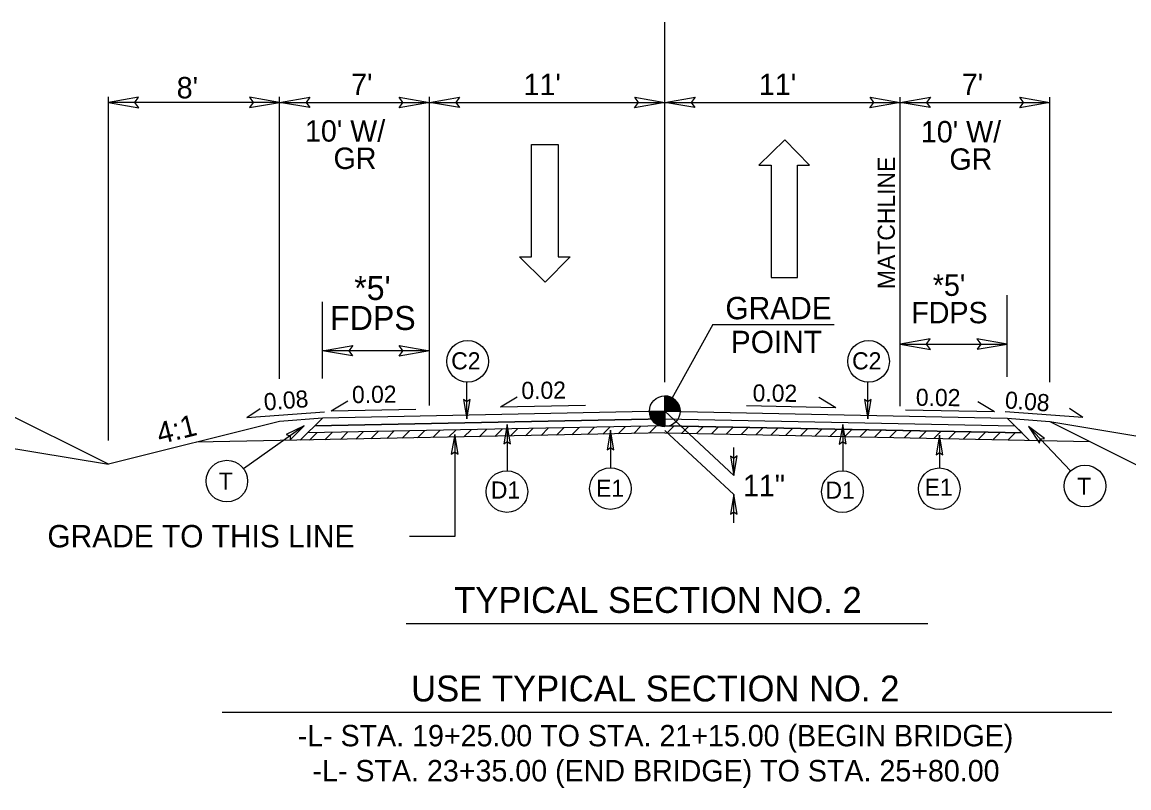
# Model space of a CAD drawing. Extents: x 1184121 to 1184397, y 1246506 to 1246661.
# Drawn here: x 1184197.8 to 1184249.5, y 1246556.8 to 1246592.6 of the extents above; entities that cross this region are included whole.
import ezdxf

# ---------------------------------------------------------------- set-up
doc = ezdxf.new("R2010")
doc.units = 0
doc.layers.add('Prop Shade Light', color=7, linetype='Continuous')
doc.layers.add('Sheet Data Field CELL', color=7, linetype='Continuous')

msp = doc.modelspace()

# ---------------------------------------------------------------- linework, layer by layer
at = {"layer": 'Prop Shade Light'}
msp.add_lwpolyline([(1184244.482, 1246573.385), (1184227.785, 1246573.719), (1184211.092, 1246573.385), (1184211.428, 1246573.722), (1184227.787, 1246574.049), (1184244.145, 1246573.722)], close=True, dxfattribs=at)
at = {"layer": 'Sheet Data Field CELL'}
for p, q in [((1184227.787, 1246575.765), (1184227.787, 1246592.571)), ((1184201.787, 1246573.031), (1184201.787, 1246589.086)), ((1184209.787, 1246575.906), (1184209.787, 1246589.086)), ((1184216.787, 1246574.661), (1184216.787, 1246589.086)), ((1184238.787, 1246574.633), (1184238.787, 1246589.069)), ((1184245.787, 1246575.765), (1184245.787, 1246589.069)), ((1184209.787, 1246588.821), (1184201.787, 1246588.821)), ((1184209.787, 1246588.821), (1184216.787, 1246588.821)), ((1184216.787, 1246588.821), (1184227.787, 1246588.821)), ((1184227.787, 1246588.821), (1184238.787, 1246588.821)), ((1184238.787, 1246588.821), (1184245.787, 1246588.821)), ((1184221.564, 1246581.612), (1184221.564, 1246586.862)), ((1184221.564, 1246586.862), (1184222.802, 1246586.862)), ((1184222.802, 1246586.862), (1184222.802, 1246581.612)), ((1184233.389, 1246587.079), (1184232.189, 1246585.898)), ((1184234.552, 1246585.898), (1184233.389, 1246587.079)), ((1184232.189, 1246585.898), (1184232.752, 1246585.898)), ((1184232.752, 1246585.898), (1184232.752, 1246580.648)), ((1184233.989, 1246580.648), (1184233.989, 1246585.898)), ((1184233.989, 1246585.898), (1184234.552, 1246585.898)), ((1184222.202, 1246580.431), (1184221.002, 1246581.612)), ((1184221.002, 1246581.612), (1184221.564, 1246581.612)), ((1184223.364, 1246581.612), (1184222.202, 1246580.431)), ((1184222.802, 1246581.612), (1184223.364, 1246581.612)), ((1184232.752, 1246580.648), (1184233.989, 1246580.648)), ((1184243.787, 1246576.013), (1184243.787, 1246579.818)), ((1184211.787, 1246575.934), (1184211.787, 1246579.506)), ((1184230.037, 1246578.445), (1184227.787, 1246574.4)), ((1184230.037, 1246578.445), (1184235.698, 1246578.445)), ((1184201.787, 1246571.92), (1184189.629, 1246577.999)), ((1184216.787, 1246577.224), (1184211.787, 1246577.224)), ((1184238.787, 1246577.537), (1184243.787, 1246577.537)), ((1184218.537, 1246574.038), (1184218.537, 1246575.759)), ((1184237.274, 1246574.038), (1184237.274, 1246575.759)), ((1184220.109, 1246574.605), (1184220.892, 1246575.078)), ((1184227.787, 1246574.4), (1184227.787, 1246575.116)), ((1184235.772, 1246574.565), (1184234.989, 1246575.039)), ((1184208.255, 1246574.104), (1184208.875, 1246574.532)), ((1184212.193, 1246574.414), (1184212.976, 1246574.887)), ((1184212.193, 1246574.414), (1184216.158, 1246574.493)), ((1184220.109, 1246574.605), (1184224.074, 1246574.684)), ((1184235.772, 1246574.565), (1184231.607, 1246574.649)), ((1184243.193, 1246574.367), (1184239.029, 1246574.45)), ((1184243.193, 1246574.367), (1184242.41, 1246574.84)), ((1184247.319, 1246574.104), (1184246.698, 1246574.532)), ((1184189.629, 1246573.946), (1184201.787, 1246571.92)), ((1184208.255, 1246574.104), (1184211.88, 1246574.376)), ((1184211.787, 1246574.08), (1184209.787, 1246573.92)), ((1184211.787, 1246574.08), (1184210.751, 1246573.045)), ((1184227.787, 1246574.049), (1184211.428, 1246573.722)), ((1184227.787, 1246574.4), (1184211.787, 1246574.08)), ((1184227.071, 1246574.4), (1184227.787, 1246574.4)), ((1184227.785, 1246573.684), (1184227.787, 1246574.4)), ((1184227.787, 1246574.4), (1184227.785, 1246573.684)), ((1184228.503, 1246574.4), (1184227.787, 1246574.4)), ((1184227.787, 1246574.4), (1184243.787, 1246574.08)), ((1184227.787, 1246574.4), (1184231.014, 1246571.4)), ((1184227.787, 1246574.049), (1184244.145, 1246573.722)), ((1184247.319, 1246574.104), (1184243.694, 1246574.376)), ((1184243.787, 1246574.08), (1184245.787, 1246573.92)), ((1184243.787, 1246574.08), (1184244.822, 1246573.044)), ((1184209.787, 1246573.92), (1184201.787, 1246571.92)), ((1184210.93, 1246573.715), (1184208.1, 1246571.717)), ((1184227.793, 1246573.719), (1184211.092, 1246573.385)), ((1184211.904, 1246573.068), (1184212.244, 1246573.408)), ((1184212.625, 1246573.082), (1184212.965, 1246573.422)), ((1184213.347, 1246573.097), (1184213.687, 1246573.437)), ((1184214.053, 1246573.111), (1184214.393, 1246573.451)), ((1184214.79, 1246573.125), (1184215.13, 1246573.466)), ((1184215.511, 1246573.14), (1184215.851, 1246573.48)), ((1184216.232, 1246573.154), (1184216.572, 1246573.494)), ((1184216.953, 1246573.169), (1184217.294, 1246573.509)), ((1184217.675, 1246573.183), (1184218.015, 1246573.523)), ((1184218.397, 1246573.198), (1184218.737, 1246573.538)), ((1184219.118, 1246573.212), (1184219.458, 1246573.552)), ((1184219.84, 1246573.226), (1184220.18, 1246573.567)), ((1184220.422, 1246573.785), (1184220.422, 1246571.619)), ((1184220.561, 1246573.241), (1184220.901, 1246573.581)), ((1184221.283, 1246573.255), (1184221.623, 1246573.595)), ((1184222.004, 1246573.27), (1184222.344, 1246573.61)), ((1184222.726, 1246573.284), (1184223.066, 1246573.624)), ((1184223.447, 1246573.299), (1184223.787, 1246573.639)), ((1184224.169, 1246573.313), (1184224.509, 1246573.653)), ((1184224.89, 1246573.327), (1184225.231, 1246573.668)), ((1184225.25, 1246573.508), (1184225.25, 1246571.762)), ((1184225.612, 1246573.342), (1184225.952, 1246573.682)), ((1184226.333, 1246573.356), (1184226.674, 1246573.696)), ((1184227.055, 1246573.371), (1184227.395, 1246573.711)), ((1184227.78, 1246573.719), (1184244.482, 1246573.385)), ((1184227.787, 1246573.507), (1184231.014, 1246570.507)), ((1184227.884, 1246573.383), (1184228.21, 1246573.71)), ((1184228.577, 1246573.369), (1184228.903, 1246573.696)), ((1184229.27, 1246573.356), (1184229.597, 1246573.682)), ((1184229.963, 1246573.342), (1184230.29, 1246573.668)), ((1184230.657, 1246573.328), (1184230.983, 1246573.654)), ((1184231.35, 1246573.314), (1184231.676, 1246573.641)), ((1184232.043, 1246573.3), (1184232.37, 1246573.627)), ((1184232.736, 1246573.286), (1184233.063, 1246573.613)), ((1184233.429, 1246573.272), (1184233.756, 1246573.599)), ((1184234.123, 1246573.258), (1184234.449, 1246573.585)), ((1184234.816, 1246573.245), (1184235.143, 1246573.571)), ((1184235.509, 1246573.231), (1184235.836, 1246573.557)), ((1184236.104, 1246573.779), (1184236.104, 1246571.613)), ((1184236.202, 1246573.217), (1184236.529, 1246573.543)), ((1184236.896, 1246573.203), (1184237.222, 1246573.53)), ((1184237.589, 1246573.189), (1184237.916, 1246573.516)), ((1184238.282, 1246573.175), (1184238.609, 1246573.502)), ((1184238.975, 1246573.161), (1184239.302, 1246573.488)), ((1184239.669, 1246573.148), (1184239.995, 1246573.474)), ((1184240.362, 1246573.134), (1184240.688, 1246573.46)), ((1184241.055, 1246573.12), (1184241.382, 1246573.446)), ((1184241.748, 1246573.106), (1184242.075, 1246573.433)), ((1184242.442, 1246573.092), (1184242.768, 1246573.419)), ((1184243.135, 1246573.078), (1184243.462, 1246573.405)), ((1184244.784, 1246573.685), (1184246.753, 1246571.611)), ((1184245.787, 1246573.92), (1184261.306, 1246571.333)), ((1184245.787, 1246573.92), (1184261.306, 1246566.16)), ((1184227.785, 1246573.385), (1184205.897, 1246572.948)), ((1184211.182, 1246573.053), (1184211.523, 1246573.393)), ((1184217.968, 1246573.307), (1184217.968, 1246568.548)), ((1184227.785, 1246573.385), (1184247.651, 1246572.988)), ((1184240.628, 1246573.275), (1184240.628, 1246571.75)), ((1184243.828, 1246573.064), (1184244.155, 1246573.391)), ((1184231.014, 1246571.4), (1184231.014, 1246572.706)), ((1184231.014, 1246569.191), (1184231.014, 1246570.507)), ((1184217.968, 1246568.548), (1184215.851, 1246568.548)), ((1184215.704, 1246564.485), (1184240.08, 1246564.485)), ((1184207.1, 1246560.35), (1184248.685, 1246560.35))]:
    msp.add_line(p, q, dxfattribs=at)
for points in [[(1184203.193, 1246589.063), (1184201.787, 1246588.821), (1184203.201, 1246588.571), (1184203.021, 1246588.821)], [(1184208.381, 1246588.579), (1184209.787, 1246588.821), (1184208.373, 1246589.071), (1184208.553, 1246588.821)], [(1184211.193, 1246588.579), (1184209.787, 1246588.821), (1184211.201, 1246589.071), (1184211.021, 1246588.821)], [(1184215.381, 1246589.063), (1184216.787, 1246588.821), (1184215.373, 1246588.571), (1184215.553, 1246588.821)], [(1184218.193, 1246588.579), (1184216.787, 1246588.821), (1184218.201, 1246589.071), (1184218.021, 1246588.821)], [(1184226.381, 1246589.063), (1184227.787, 1246588.821), (1184226.373, 1246588.571), (1184226.553, 1246588.821)], [(1184229.193, 1246588.579), (1184227.787, 1246588.821), (1184229.201, 1246589.071), (1184229.021, 1246588.821)], [(1184237.381, 1246589.063), (1184238.787, 1246588.821), (1184237.373, 1246588.571), (1184237.553, 1246588.821)], [(1184240.193, 1246588.579), (1184238.787, 1246588.821), (1184240.201, 1246589.071), (1184240.021, 1246588.821)], [(1184244.381, 1246589.063), (1184245.787, 1246588.821), (1184244.373, 1246588.571), (1184244.553, 1246588.821)], [(1184240.193, 1246577.779), (1184238.787, 1246577.537), (1184240.201, 1246577.287), (1184240.021, 1246577.537)], [(1184242.381, 1246577.295), (1184243.787, 1246577.537), (1184242.373, 1246577.787), (1184242.553, 1246577.537)], [(1184213.193, 1246576.982), (1184211.787, 1246577.224), (1184213.201, 1246577.474), (1184213.021, 1246577.224)], [(1184215.381, 1246577.466), (1184216.787, 1246577.224), (1184215.373, 1246576.974), (1184215.553, 1246577.224)], [(1184218.38, 1246574.947), (1184218.537, 1246574.038), (1184218.699, 1246574.952), (1184218.537, 1246574.836)], [(1184237.117, 1246574.947), (1184237.274, 1246574.038), (1184237.436, 1246574.952), (1184237.274, 1246574.836)], [(1184210.277, 1246573.062), (1184210.93, 1246573.715), (1184210.089, 1246573.32), (1184210.277, 1246573.254)], [(1184220.579, 1246572.875), (1184220.422, 1246573.785), (1184220.26, 1246572.87), (1184220.422, 1246572.987)], [(1184225.406, 1246572.599), (1184225.25, 1246573.508), (1184225.088, 1246572.593), (1184225.25, 1246572.71)], [(1184236.26, 1246572.87), (1184236.104, 1246573.779), (1184235.942, 1246572.865), (1184236.104, 1246572.981)], [(1184245.524, 1246573.133), (1184244.784, 1246573.685), (1184245.297, 1246572.91), (1184245.334, 1246573.106)], [(1184218.125, 1246572.397), (1184217.968, 1246573.307), (1184217.807, 1246572.392), (1184217.968, 1246572.509)], [(1184240.785, 1246572.366), (1184240.628, 1246573.275), (1184240.466, 1246572.361), (1184240.628, 1246572.477)], [(1184230.857, 1246572.309), (1184231.014, 1246571.4), (1184231.175, 1246572.315), (1184231.014, 1246572.198)], [(1184231.171, 1246569.597), (1184231.014, 1246570.507), (1184230.853, 1246569.592), (1184231.014, 1246569.708)]]:
    msp.add_lwpolyline(points, close=True, dxfattribs=at)
for points in [[(1184227.793, 1246575.116), (1184227.793, 1246575.116), (1184227.793, 1246574.4)], [(1184227.808, 1246575.116), (1184227.808, 1246574.4)], [(1184227.822, 1246575.115), (1184227.822, 1246574.4)], [(1184227.836, 1246575.115), (1184227.836, 1246574.4)], [(1184227.851, 1246575.113), (1184227.851, 1246574.4)], [(1184227.865, 1246575.111), (1184227.865, 1246574.4)], [(1184227.879, 1246575.11), (1184227.879, 1246574.4)], [(1184227.894, 1246575.108), (1184227.894, 1246574.4)], [(1184227.908, 1246575.107), (1184227.908, 1246574.4)], [(1184227.922, 1246575.103), (1184227.922, 1246574.4)], [(1184227.936, 1246575.1), (1184227.936, 1246574.4)], [(1184227.951, 1246575.097), (1184227.951, 1246574.4)], [(1184227.965, 1246575.094), (1184227.965, 1246574.4)], [(1184227.979, 1246575.089), (1184227.979, 1246574.4)], [(1184227.994, 1246575.086), (1184227.994, 1246574.4)], [(1184228.008, 1246575.081), (1184228.008, 1246574.4)], [(1184228.022, 1246575.076), (1184228.022, 1246574.4)], [(1184228.037, 1246575.072), (1184228.037, 1246574.4)], [(1184228.051, 1246575.065), (1184228.051, 1246574.4)], [(1184228.065, 1246575.059), (1184228.065, 1246574.4)], [(1184228.08, 1246575.052), (1184228.08, 1246574.4)], [(1184228.094, 1246575.046), (1184228.094, 1246574.4)], [(1184228.108, 1246575.04), (1184228.108, 1246574.4)], [(1184228.123, 1246575.032), (1184228.123, 1246574.4)], [(1184228.137, 1246575.024), (1184228.137, 1246574.4)], [(1184228.151, 1246575.016), (1184228.151, 1246574.4)], [(1184228.166, 1246575.008), (1184228.166, 1246574.4)], [(1184228.18, 1246574.998), (1184228.18, 1246574.4)], [(1184228.194, 1246574.989), (1184228.194, 1246574.4)], [(1184228.209, 1246574.978), (1184228.209, 1246574.4)], [(1184228.223, 1246574.968), (1184228.223, 1246574.4)], [(1184228.237, 1246574.957), (1184228.237, 1246574.4)], [(1184228.252, 1246574.944), (1184228.252, 1246574.4)], [(1184228.266, 1246574.932), (1184228.266, 1246574.4)], [(1184228.28, 1246574.919), (1184228.28, 1246574.4)], [(1184228.295, 1246574.904), (1184228.295, 1246574.4)], [(1184228.309, 1246574.89), (1184228.309, 1246574.4)], [(1184228.323, 1246574.874), (1184228.323, 1246574.4)], [(1184228.338, 1246574.857), (1184228.338, 1246574.4)], [(1184228.352, 1246574.839), (1184228.352, 1246574.4)], [(1184228.366, 1246574.82), (1184228.366, 1246574.4)], [(1184228.381, 1246574.799), (1184228.381, 1246574.4)], [(1184228.395, 1246574.777), (1184228.395, 1246574.4)], [(1184228.409, 1246574.753), (1184228.409, 1246574.4)], [(1184228.423, 1246574.728), (1184228.423, 1246574.4)], [(1184228.438, 1246574.698), (1184228.438, 1246574.4)], [(1184228.452, 1246574.664), (1184228.452, 1246574.4)], [(1184228.466, 1246574.624), (1184228.466, 1246574.4)], [(1184228.481, 1246574.575), (1184228.481, 1246574.4)], [(1184228.495, 1246574.502), (1184228.495, 1246574.4)], [(1184227.074, 1246574.4), (1184227.074, 1246574.322)], [(1184227.088, 1246574.4), (1184227.088, 1246574.238)], [(1184227.103, 1246574.4), (1184227.103, 1246574.187)], [(1184227.117, 1246574.4), (1184227.117, 1246574.144)], [(1184227.131, 1246574.4), (1184227.131, 1246574.11)], [(1184227.146, 1246574.4), (1184227.146, 1246574.08)], [(1184227.16, 1246574.4), (1184227.16, 1246574.053)], [(1184227.174, 1246574.4), (1184227.174, 1246574.028)], [(1184227.189, 1246574.4), (1184227.189, 1246574.005)], [(1184227.203, 1246574.4), (1184227.203, 1246573.985)], [(1184227.217, 1246574.4), (1184227.217, 1246573.966)], [(1184227.231, 1246574.4), (1184227.231, 1246573.948)], [(1184227.246, 1246574.4), (1184227.246, 1246573.931)], [(1184227.26, 1246574.4), (1184227.26, 1246573.915)], [(1184227.274, 1246574.4), (1184227.274, 1246573.899)], [(1184227.289, 1246574.4), (1184227.289, 1246573.884)], [(1184227.303, 1246574.4), (1184227.303, 1246573.872)], [(1184227.317, 1246574.4), (1184227.317, 1246573.859)], [(1184227.332, 1246574.4), (1184227.332, 1246573.846)], [(1184227.346, 1246574.4), (1184227.346, 1246573.835)], [(1184227.36, 1246574.4), (1184227.36, 1246573.824)], [(1184227.375, 1246574.4), (1184227.375, 1246573.814)], [(1184227.389, 1246574.4), (1184227.389, 1246573.805)], [(1184227.403, 1246574.4), (1184227.403, 1246573.795)], [(1184227.418, 1246574.4), (1184227.418, 1246573.786)], [(1184227.432, 1246574.4), (1184227.432, 1246573.778)], [(1184227.446, 1246574.4), (1184227.446, 1246573.77)], [(1184227.461, 1246574.4), (1184227.461, 1246573.762)], [(1184227.475, 1246574.4), (1184227.475, 1246573.755)], [(1184227.489, 1246574.4), (1184227.489, 1246573.749)], [(1184227.504, 1246574.4), (1184227.504, 1246573.743)], [(1184227.518, 1246574.4), (1184227.518, 1246573.736)], [(1184227.532, 1246574.4), (1184227.532, 1246573.73)], [(1184227.547, 1246574.4), (1184227.547, 1246573.725)], [(1184227.561, 1246574.4), (1184227.561, 1246573.72)], [(1184227.575, 1246574.4), (1184227.575, 1246573.716)], [(1184227.59, 1246574.4), (1184227.59, 1246573.712)], [(1184227.604, 1246574.4), (1184227.604, 1246573.708)], [(1184227.618, 1246574.4), (1184227.618, 1246573.705)], [(1184227.633, 1246574.4), (1184227.633, 1246573.701)], [(1184227.647, 1246574.4), (1184227.647, 1246573.698)], [(1184227.661, 1246574.4), (1184227.661, 1246573.695)], [(1184227.675, 1246574.4), (1184227.675, 1246573.693)], [(1184227.69, 1246574.4), (1184227.69, 1246573.69)], [(1184227.704, 1246574.4), (1184227.704, 1246573.689)], [(1184227.718, 1246574.4), (1184227.718, 1246573.687)], [(1184227.733, 1246574.4), (1184227.733, 1246573.685)], [(1184227.747, 1246574.4), (1184227.747, 1246573.685)], [(1184227.761, 1246574.4), (1184227.761, 1246573.684)], [(1184227.776, 1246574.4), (1184227.776, 1246573.684), (1184227.776, 1246573.684)]]:
    msp.add_lwpolyline(points, dxfattribs=at)
for centre, radius in [((1184218.573, 1246576.73), 0.972), ((1184237.31, 1246576.73), 0.972), ((1184227.786, 1246574.4), 0.716), ((1184207.322, 1246571.136), 0.972), ((1184247.422, 1246570.906), 0.972), ((1184220.408, 1246570.647), 0.972), ((1184225.248, 1246570.79), 0.972), ((1184236.089, 1246570.641), 0.972), ((1184240.614, 1246570.778), 0.972)]:
    msp.add_circle(centre, radius, dxfattribs=at)
for start, end in [(359.9905, 89.9905), (179.9905, 269.9905)]:
    msp.add_arc((1184227.786, 1246574.4), 0.716, start, end, dxfattribs=at)

# ---------------------------------------------------------------- texts
for s, height, rotation, p in [("8'", 1, 359.9998, (1184204.978, 1246589.011)), ("7'", 1, 359.9998, (1184213.128, 1246589.162)), ("11'", 1, 359.9998, (1184221.187, 1246589.161)), ("11'", 1, 359.9998, (1184232.187, 1246589.162)), ("7'", 1, 359.9998, (1184241.665, 1246589.161)), ("10' W/", 1, 359.9998, (1184210.974, 1246586.992)), ("10' W/", 1, 359.9998, (1184239.754, 1246586.955)), ('GR', 1, 359.9998, (1184212.307, 1246585.712)), ('GR', 1, 359.9998, (1184241.087, 1246585.675)), ('MATCHLINE', 0.8, 90, (1184238.537, 1246580.106)), ("*5' ", 1.12, 359.9998, (1184213.275, 1246579.595)), ("*5' ", 1, 359.9998, (1184240.311, 1246579.787)), ('FDPS', 1.12, 359.9998, (1184212.151, 1246578.195)), ('FDPS', 1, 359.9998, (1184239.307, 1246578.507)), ('0.02', 0.8, 0.5402, (1184213.173, 1246574.778)), ('0.02', 0.8, 0.5402, (1184221.089, 1246574.969)), ('0.02', 0.8, 359.4598, (1184231.889, 1246574.855)), ('0.08', 0.8, 4.5736, (1184209.08, 1246574.43)), ('0.02', 0.8, 359.4598, (1184239.517, 1246574.653)), ('0.08', 0.8, 355.7746, (1184243.661, 1246574.535)), ('4:1', 1, 14.036, (1184204.188, 1246572.853)), ('T', 0.8, 359.9997, (1184206.942, 1246570.734)), ('11"', 1, 359.9998, (1184231.442, 1246570.431)), ('T', 0.8, 359.9997, (1184247.054, 1246570.498)), ('-L- STA. 19+25.00 TO STA. 21+15.00 (BEGIN BRIDGE)', 1, 0.0002, (1184210.629, 1246558.75)), ('-L- STA. 23+35.00 (END BRIDGE) TO STA. 25+80.00', 1, 0.0002, (1184211.324, 1246557.112))]:
    msp.add_text(s, height=height, rotation=rotation, dxfattribs=at).set_placement(p)
for s, height, p in [('GRADE', 1.044, (1184230.62, 1246578.695)), ('POINT', 1.044, (1184230.871, 1246577.113)), ('C2', 0.8, (1184217.806, 1246576.354)), ('C2', 0.8, (1184236.541, 1246576.354)), ('D1', 0.8, (1184219.66, 1246570.32)), ('E1', 0.8, (1184224.576, 1246570.405)), ('D1', 0.8, (1184235.296, 1246570.314)), ('E1', 0.8, (1184239.929, 1246570.452)), ('GRADE TO THIS LINE', 1.04396, (1184198.937, 1246568.043)), ('TYPICAL SECTION NO. 2', 1.20892, (1184217.944, 1246564.982)), ('USE TYPICAL SECTION NO. 2', 1.20892, (1184215.934, 1246560.846))]:
    msp.add_text(s, height=height, dxfattribs=at).set_placement(p)

doc.saveas('drawing.dxf')
